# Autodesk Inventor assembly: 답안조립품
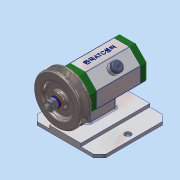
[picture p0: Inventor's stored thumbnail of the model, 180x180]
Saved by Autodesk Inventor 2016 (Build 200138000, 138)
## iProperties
Created: 2018-06
Part Number: 답안조립품
Material: 일반
Document SubType Name: Assembly
Designer: 605-17
Author: 605-17
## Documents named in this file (16)
- C:\Users\605-17\Desktop\480607V1015\답안조립품.iam
- C:\Users\605-17\Desktop\480607V1015\본체.ipt
- C:\Users\605-17\Desktop\480607V1015\뒤커버.ipt
- C:\Users\605-17\Desktop\480607V1015\앞커버.ipt
- C:\Users\605-17\Desktop\480607V1015\볼트 M4x12.ipt
- C:\Users\605-17\Desktop\480607V1015\오일 실 15 25 7.ipt
- C:\Users\605-17\Desktop\480607V1015\베어링 15x32x9.ipt
- C:\Users\605-17\Desktop\480607V1015\축.ipt
- C:\Users\605-17\Desktop\480607V1015\키 3x3x12.ipt
- 키 3x3x12.ipt
- C:\Users\605-17\Desktop\480607V1015\V벨트풀리.ipt
- C:\Users\605-17\Desktop\480607V1015\와셔 8x17.ipt
- C:\Users\605-17\Desktop\480607V1015\스프링와셔 8.ipt
- C:\Users\605-17\Desktop\480607V1015\너트 M8.ipt
- 너트 M8.ipt
- C:\Users\605-17\Desktop\480607V1015\고무캡.ipt
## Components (2 placed, 2 different names)
1. V벨트풀리:1 — 각도:2
2. 고무캡:1
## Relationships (1: Angle 1)
- 각도:2 [Angle]: V벨트풀리:1
